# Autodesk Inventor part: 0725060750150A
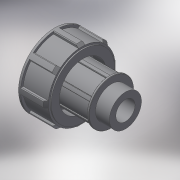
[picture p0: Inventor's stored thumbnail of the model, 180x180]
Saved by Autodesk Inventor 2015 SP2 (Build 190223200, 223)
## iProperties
Created: 2017-04
Part Number: 0725060750150A
Material: Generic
Description: PLASSON THREADED ADAPTOR 75-1.1/2"
Document SubType Name: Modeling
Designer: KIM
Density: 1 g/cm^3
Appearance: Default
Author: KIM
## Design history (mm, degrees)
derived "07250.ipt"
feature "Solid1::07250.ipt"
tag "TaggingFeature1"
body "Solid1"
other parameters: "d1" = 47.803, "d2" = 128, "d3" = 22, "d6" = 134, "d7" = 124.62, "d8" = 107.2, "d9" = 75, "d10" = 81.2651, "d12" = 28.6818, "d13" = 38.2424, "d14" = 25.3, "d15" = 100.5, "d16" = 3.84, "d17" = 51.2, "d18" = 22, "d19" = 26.4, "d24" = 9.5606, "d25" = 4.7803, "d27" = 0, "d28" = 3.82424, "d31" = 0.95606, "d35" = 360 deg, "d41" = 29.337, "d56" = 78.75, "d57" = 7.5, "d58" = 3.75, "d60" = 0, "d61" = 0.47803, "d64" = 0.47803, "d68" = 360 deg, "d_" = 75, "R_" = 47.803, "E_" = 134, "H_" = 128, "l_2" = 22, "d55" = 75
